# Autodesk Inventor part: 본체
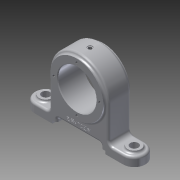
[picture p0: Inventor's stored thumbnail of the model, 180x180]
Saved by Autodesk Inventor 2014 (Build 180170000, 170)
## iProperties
Created: 2019-05
Part Number: 본체
Material: Aluminum 6061
Document SubType Name: Modeling
Designer: kh
Density: 2.71 g/cm^3
Appearance: Aluminum - Flat
Mass: 453.266 g
Surface Area: 315.114 cm^2
Volume: 167.257 cm^3
Author: kh
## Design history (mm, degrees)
sketch "Sketch1"
  geometry: L1 (-60, -15)-(60, -15); L2 (60, 15)-(-60, 15); L3 (0, 15)-(0, -15); A1 r 15 centre (60, 0) between (60, -15) and (60, 15); A2 r 15 centre (-60, 0) between (-60, 15) and (-60, -15); 2 further points
  constraints: 6 end point, 4 point on circle, 3 midpoint, 2 centre point, 1 coincident, 1 horizontal, 1 parallel, 1 tangent, 1 vertical
  dimensions: "d0" = 120 distance of L2.start L2.end; "d2" = 30 distance of L1.end L2.start; "d3" = 15 radius of A1; "d4" = 15 radius of A2; "d5" = 150 dimension on A1 A2 (derived)
extrude "Extrusion1" new body sketch "Sketch1" distance "d6" = 12; taper "d7" = 0 deg
sketch "Sketch2"
  geometry: C1 r 9 at (-60, 0); C2 r 9 at (60, 0); A1 r 15 centre (60, 0) between (60, -15) and (60, 15) reference; A2 r 15 centre (-60, 0) between (-60, 15) and (-60, -15) reference; 1 further point
  constraints: 2 centre point, 2 coincident
  dimensions: "d8" = 9 radius of C1; "d9" = 9 radius of C2
extrude "Extrusion2" join sketch "Sketch2" distance "d10" = 3; taper "d11" = 0 deg
sketch "Sketch4"
  geometry: L1 (-60, 0)-(60, 0) reference; L2 (-60, 12)-(60, 12) reference; L3 (40, 60)-(40, 12); L4 (-40, 60)-(-40, 12); L5 (-40, 12)-(40, 12); C1 r 36 at (0, 60); A1 r 40 centre (0, 60) between (40, 60) and (-40, 60); 2 further points
  constraints: 6 end point, 2 centre point, 2 perpendicular, 2 point on circle, 2 point on line, 2 tangent, 1 coincident, 1 collinear, 1 midpoint, 1 vertical alignment
  dimensions: "d12" = 40 radius of A1; "d13" = 60 distance from line of L1 A1.centre; "d86" = 36 radius of C1
extrude "Extrusion3" join sketch "Sketch4" stored distance "d14" = 30; taper "d15" = 0 deg
extrude "Extrusion4" join sketch "Sketch4" stored distance "d16" = 30; taper "d17" = 0 deg
sketch "Sketch10"
  geometry: C1 r 36 at (0, 60); 1 further point
  constraints: 1 centre point, 1 vertical alignment
  dimensions: "d91" = 36 radius of C1; "d92" = 60 distance of point (0, 0) C1.centre
extrude "Extrusion6" join sketch "Sketch10" stored distance "d93" = 36; taper "d94" = 0 deg
hole "Hole2" diameter "d29" = 11; stored, may be unused: countersink angle "d33" = 90 deg, drill point angle "d35" = 118 deg; dims "d27" = 10, "d28" = 10, "d30" = 6, "d31" = 4, "d32" = 2, "d34" = 8
hole "Hole3" diameter "d38" = 11; stored, may be unused: countersink angle "d42" = 90 deg, drill point angle "d44" = 118 deg; dims "d36" = 10, "d37" = 10, "d39" = 6, "d40" = 4, "d41" = 2, "d43" = 8
workplane "Work Plane1"
sketch "Sketch7"
  geometry: 4 further points
  constraints: 3 coincident
hole "Hole6" sketch "Sketch7" at (0, 0) diameter "d65" = 4.917; stored, may be unused: countersink angle "d69" = 90 deg, drill point angle "d71" = 118 deg; dims "d66" = 8, "d67" = 7, "d68" = 1, "d70" = 10
fillet "Fillet1" dims "d82" = 6
fillet "Fillet2" dims "d83" = 3
fillet "Fillet3" dims "d84" = 3
hole "Hole8" diameter "d97" = 52; stored, may be unused: countersink angle "d101" = 90 deg, drill point angle "d103" = 118 deg; dims "d95" = 10, "d96" = 10, "d98" = 2, "d99" = 19.05, "d100" = 4.775, "d102" = 8
sketch "Sketch11"
  geometry: L1 (0, 0)-(0, -31); C1 r 36 at (0, 0) reference; 2 further points
  constraints: 2 end point, 1 coincident, 1 vertical
  dimensions: "d104" = 31 distance of L1.start L1.end
hole "Hole9" sketch "Sketch11" at (0, -31) diameter "d105" = 3.242; stored, may be unused: countersink angle "d109" = 90 deg, drill point angle "d111" = 118 deg; dims "d106" = 6, "d107" = 19.05, "d108" = 4.775, "d110" = 8
pattern_circular "Circular Pattern2" dims angle "d113" = 360 deg
mirror "Mirror2"
sketch "Sketch12"
  geometry: L1 (0, 0)-(0, -26); C1 r 36 at (0, 0) reference; 2 further points
  constraints: 2 coincident, 2 end point, 1 vertical
  dimensions: "d115" = 26 distance of L1.start L1.end
hole "Hole10" sketch "Sketch12" at (0, -26) diameter "d116" = 3; stored, may be unused: countersink angle "d120" = 90 deg, drill point angle "d122" = 118 deg; dims "d117" = 6, "d118" = 19.05, "d119" = 4.775, "d121" = 8
fillet "Fillet5" dims "d123" = 3
chamfer "Chamfer2" distance "d124" = 1; stored, may be unused: second distance "d125" = 2, angle "d126" = 45 deg
sketch "Sketch14"
  geometry: L1 (120, 0)-(0, 0) reference; L2 (23, -47.671)-(23, -18) reference; L3 (96, 0)-(96, -4); L4 (96, -4)-(90, -4); L5 (90, -4)-(90, -10); L6 (90, -10)-(30, -10); L7 (30, -10)-(30, -4); L8 (30, -4)-(24, -4); L9 (24, -4)-(24, 0); L10 (96, 0)-(24, 0); 3 further points
  constraints: 16 end point, 4 perpendicular, 3 parallel, 2 equal length, 2 midpoint, 2 point on line, 1 coincident, 1 collinear
  dimensions: "d128" = 4 distance of L3.start L3.end; "d129" = 6 distance of L4.end L5.end; "d130" = 60 distance of L5.end L6.end; "d131" = 72 distance of L3.start L9.end
extrude "Extrusion7" cut sketch "Sketch14" stored distance "d132" = 36; taper "d133" = 0 deg
fillet "Fillet6" dims "d134" = 3
fillet "Fillet7" dims "d135" = 3
workplane "Work Plane3"
sketch "Sketch15"
  geometry: L1 (76.592, -10.402)-(43.408, -10.402); L2 (43.408, -10.402)-(43.408, -5.598); L3 (43.408, -5.598)-(76.592, -5.598); L4 (76.592, -5.598)-(76.592, -10.402); L5 (76.592, -10.402)-(43.408, -5.598); L6 (76.592, -5.598)-(43.408, -10.402); L7 (87, -1)-(33, -1) reference; 3 further points
  constraints: 4 end point, 2 midpoint, 1 vertical alignment, 2 other
  dimensions: "d137" = 7 distance from line of L7 point (60, -8)
emboss "Emboss1" sketch "Sketch15" dims "d0" = 120, "d2" = 30, "d3" = 15, "d4" = 15, "d5" = 150 (derived), "d12" = 40, "d13" = 60, "d86" = 36, "d138" = 0.5, "d139" = 0
sketch "Sketch16"
  geometry: 2 further points
  constraints: 1 coincident
hole "Hole11" sketch "Sketch16" at (0, 0) diameter "d140" = 2; stored, may be unused: countersink angle "d144" = 90 deg, drill point angle "d146" = 0 deg; dims "d141" = 6, "d142" = 4, "d143" = 2, "d145" = 20
body "Solid1"
other parameters: "d136" = 44
